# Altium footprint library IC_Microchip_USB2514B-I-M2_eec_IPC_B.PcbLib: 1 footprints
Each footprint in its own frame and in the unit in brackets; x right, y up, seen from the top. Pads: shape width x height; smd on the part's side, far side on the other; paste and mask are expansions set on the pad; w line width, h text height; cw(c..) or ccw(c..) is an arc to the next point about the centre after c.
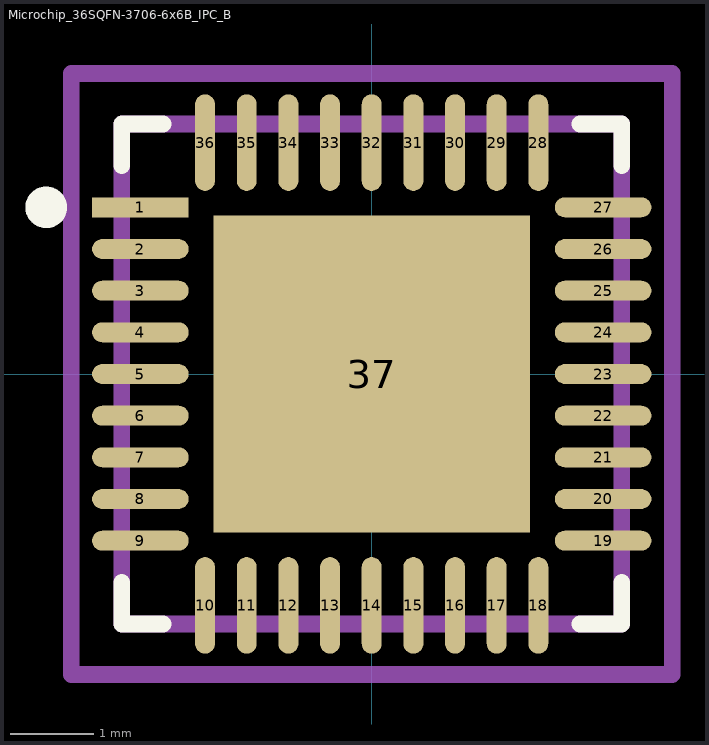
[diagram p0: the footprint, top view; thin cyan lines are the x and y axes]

## Microchip_36SQFN-3706-6x6B_IPC_B [mm]
pads (37):
  rect 1.159x0.239 smd paste+0 mask+0: 1(-2.777,2)
  rrect100% 1.159x0.239 smd paste+0 mask+0: 2(-2.777,1.5) 3(-2.777,1) 4(-2.777,0.5) 5(-2.777,0) 6(-2.777,-0.5) 7(-2.777,-1) 8(-2.777,-1.5) 9(-2.777,-2) 19(2.777,-2) 20(2.777,-1.5) 21(2.777,-1) 22(2.777,-0.5) 23(2.777,0) 24(2.777,0.5) 25(2.777,1) 26(2.777,1.5) 27(2.777,2)
  rrect100% 0.239x1.159 smd paste+0 mask+0: 10(-2,-2.777) 11(-1.5,-2.777) 12(-1,-2.777) 13(-0.5,-2.777) 14(0,-2.777) 15(0.5,-2.777) 16(1,-2.777) 17(1.5,-2.777) 18(2,-2.777) 28(2,2.777) 29(1.5,2.777) 30(1,2.777) 31(0.5,2.777) 32(0,2.777) 33(-0.5,2.777) 34(-1,2.777) 35(-1.5,2.777) 36(-2,2.777)
  rect 3.8x3.8 smd paste-1000 mask+0: 37(0,0)
Top Overlay:
  circle w0.25: c-3.906,2 r0.125
  lines w0.2: -3,-2.5 -3,-3 -2.5,-3 ; -3,2.5 -3,3 -2.5,3 ; 2.5,-3 3,-3 3,-2.5 ; 2.5,3 3,3 3,2.5
Top Paste:
  rectangle: -1.202,-1.202 1.202,1.202
Mechanical 10:
  lines w0.2: -3.606,-3.606 3.606,-3.606 3.606,3.606 -3.606,3.606 -3.606,-3.606
  text ".Designator" at 0,0.188 h1
Mechanical 12:
  lines w0.2: -3,-3 3,-3 3,3 -3,3 -3,-3
Mechanical 15:
  lines w0.1: -0.5,0 0.5,0 ; 0,-0.5 0,0.5
  lines w0.2: -3.606,-3.606 3.606,-3.606 3.606,3.606 -3.606,3.606 -3.606,-3.606
3D body "IC_Microchip_USB2514B-I-M2_eec.STEP": height 0.25, standoff 0, extent -3.606,-3.606 3.606,3.606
